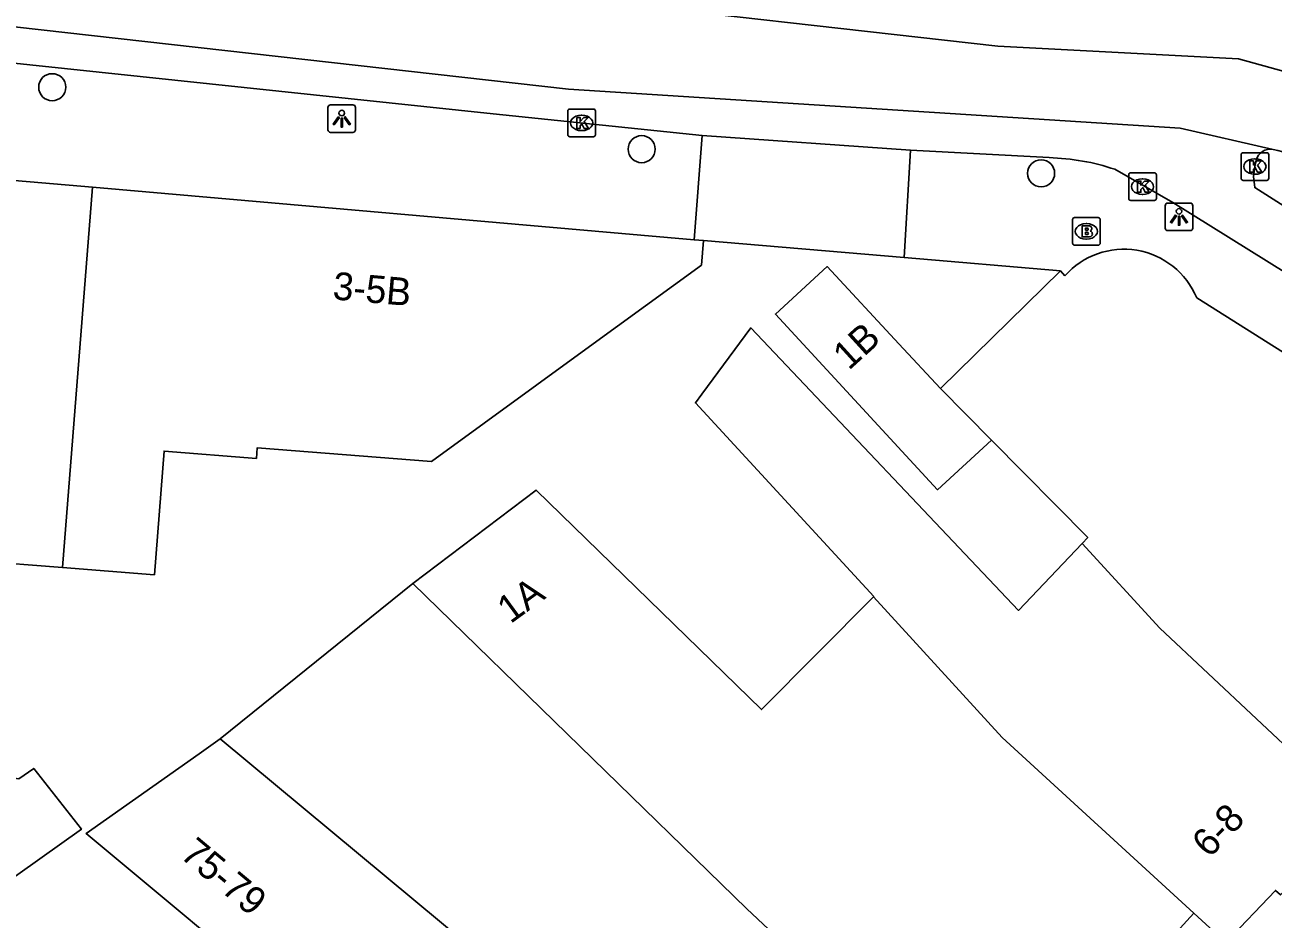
# Model space of a CAD drawing. Extents: x 160664 to 161506, y 382245 to 383288.
# Drawn here: x 160915.93 to 160961.04, y 382898.51 to 382930.82 of the extents above; entities that cross this region are included whole.
import ezdxf

# ---------------------------------------------------------------- set-up
doc = ezdxf.new("R2010")
doc.units = 0
for name, color, linetype in [('IMGEO_Boom', 7, 'Continuous'), ('IMGEO_Brandkraan', 7, 'Continuous'), ('IMGEO_Fietspad_gesloten', 7, 'Continuous'), ('IMGEO_Kolk', 7, 'Continuous'), ('IMGEO_Lichtpunt', 7, 'Continuous'), ('IMGEO_OVBaan_gesloten', 7, 'Continuous'), ('IMGEO_Pand', 7, 'Continuous'), ('IMGEO_Pand_nummerreeks', 7, 'Continuous'), ('IMGEO_Voetpad_open', 7, 'Continuous')]:
    doc.layers.add(name, color=color, linetype=linetype)

msp = doc.modelspace()

# ---------------------------------------------------------------- linework, layer by layer
at = {"layer": 'IMGEO_Boom'}
for centre in [(160916.911, 382928.573), (160938.215, 382926.333), (160952.653, 382925.461)]:
    msp.add_circle(centre, 0.489, dxfattribs=at)
at = {"layer": 'IMGEO_Brandkraan'}
for p, q in [((160953.787, 382922.935), (160953.787, 382923.787)), ((160953.862, 382923.861), (160954.714, 382923.861)), ((160954.275, 382923.641), (160954.3, 382923.641)), ((160954.788, 382923.787), (160954.788, 382922.935)), ((160954.714, 382922.861), (160953.862, 382922.861)), ((160954.298, 382923.081), (160954.273, 382923.081))]:
    msp.add_line(p, q, dxfattribs=at)
for points in [[(160953.787, 382922.935), (160953.787, 382923.787)], [(160953.862, 382923.861), (160954.714, 382923.861)], [(160954.788, 382923.787), (160954.788, 382922.935)], [(160954.135, 382923.561), (160954.135, 382923.161), (160954.348, 382923.161)], [(160954.366, 382923.561), (160954.135, 382923.561)], [(160954.314, 382923.48), (160954.26, 382923.48), (160954.26, 382923.404)], [(160954.26, 382923.404), (160954.313, 382923.404)], [(160954.322, 382923.328), (160954.26, 382923.328), (160954.26, 382923.247)], [(160954.26, 382923.247), (160954.322, 382923.247)], [(160954.714, 382922.861), (160953.862, 382922.861)]]:
    msp.add_lwpolyline(points, dxfattribs=at)
for centre, radius, start, end in [((160953.864, 382923.785), 0.0765, 91.552, 178.448), ((160953.864, 382923.785), 0.0765, 91.552, 178.448), ((160954.712, 382923.785), 0.0765, 1.552, 88.448), ((160954.712, 382923.785), 0.0765, 1.552, 88.448), ((160954.315, 382923.442), 0.0379, 267.8285, 90.9355), ((160954.323, 382923.287), 0.0404, 269.8759, 90.5077), ((160954.354, 382923.412), 0.251, 268.6676, 293.5347), ((160954.37, 382923.416), 0.145, 59.4692, 91.5367), ((160954.395, 382923.463), 0.0922, 285.5137, 58.1501), ((160954.4, 382923.271), 0.105, 301.3115, 78.989), ((160953.864, 382922.937), 0.0765, 181.552, 268.448), ((160953.864, 382922.937), 0.0765, 181.552, 268.448), ((160954.712, 382922.937), 0.0765, 271.552, 358.448), ((160954.712, 382922.937), 0.0765, 271.552, 358.448)]:
    msp.add_arc(centre, radius, start, end, dxfattribs=at)
for centre, major_axis, ratio, start_param, end_param in [((160954.274, 382923.361), (-0.387, 0.002), 0.722429, 4.712389, 7.853982), ((160954.299, 382923.361), (-0.39, 0.002), 0.717154, 1.570796, 4.712389)]:
    msp.add_ellipse(centre, major_axis=major_axis, ratio=ratio, start_param=start_param, end_param=end_param, dxfattribs=at)
at = {"layer": 'IMGEO_Fietspad_gesloten'}
for points in [[(160940.406, 382926.828), (160932.851, 382927.616), (160914.84, 382929.519), (160910.629, 382929.789), (160910.39, 382929.798)], [(160940.406, 382926.828), (160947.93, 382926.301)], [(160947.93, 382926.301), (160952.94, 382926.027)], [(160960.425, 382925.941), (160960.379, 382925.705), (160960.333, 382925.349), (160960.377, 382924.944), (160961.434, 382924.276)], [(160955.322, 382925.605), (160957.414, 382924.41), (160972.521, 382914.992), (160974.161, 382913.943)]]:
    msp.add_lwpolyline(points, dxfattribs=at)
for centre, radius, start, end in [((160952.712, 382917.807), 8.223, 71.4953, 88.4119), ((160960.928, 382925.812), 0.519, 78.1045, 165.6018)]:
    msp.add_arc(centre, radius, start, end, dxfattribs=at)
at = {"layer": 'IMGEO_Kolk'}
for p, q in [((160935.545, 382926.857), (160935.545, 382927.709)), ((160935.62, 382927.783), (160936.472, 382927.783)), ((160936.546, 382927.709), (160936.546, 382926.857)), ((160936.033, 382927.563), (160936.058, 382927.563)), ((160936.056, 382927.003), (160936.031, 382927.003)), ((160936.472, 382926.783), (160935.62, 382926.783)), ((160959.879, 382925.28), (160959.879, 382926.132)), ((160959.954, 382926.206), (160960.806, 382926.206)), ((160960.367, 382925.986), (160960.392, 382925.986)), ((160960.88, 382926.132), (160960.88, 382925.28)), ((160955.893, 382925.478), (160956.745, 382925.478)), ((160955.818, 382924.552), (160955.818, 382925.404)), ((160956.306, 382925.258), (160956.331, 382925.258)), ((160956.819, 382925.404), (160956.819, 382924.552)), ((160960.806, 382925.206), (160959.954, 382925.206)), ((160960.39, 382925.426), (160960.365, 382925.426)), ((160956.329, 382924.698), (160956.304, 382924.698)), ((160956.745, 382924.478), (160955.893, 382924.478))]:
    msp.add_line(p, q, dxfattribs=at)
for points in [[(160935.545, 382926.857), (160935.545, 382927.709)], [(160935.62, 382927.783), (160936.472, 382927.783)], [(160936.546, 382927.709), (160936.546, 382926.857)], [(160935.866, 382927.483), (160935.989, 382927.483), (160935.989, 382927.332), (160936.119, 382927.483), (160936.283, 382927.483), (160936.137, 382927.332), (160936.29, 382927.083), (160936.138, 382927.083), (160936.053, 382927.247), (160935.989, 382927.18), (160935.989, 382927.083), (160935.866, 382927.083), (160935.866, 382927.483)], [(160936.472, 382926.783), (160935.62, 382926.783)], [(160959.879, 382925.28), (160959.879, 382926.132)], [(160959.954, 382926.206), (160960.806, 382926.206)], [(160960.2, 382925.906), (160960.323, 382925.906), (160960.323, 382925.755), (160960.453, 382925.906), (160960.617, 382925.906), (160960.471, 382925.755), (160960.624, 382925.506), (160960.472, 382925.506), (160960.387, 382925.67), (160960.323, 382925.603), (160960.323, 382925.506), (160960.2, 382925.506), (160960.2, 382925.906)], [(160960.88, 382926.132), (160960.88, 382925.28)], [(160955.893, 382925.478), (160956.745, 382925.478)], [(160955.818, 382924.552), (160955.818, 382925.404)], [(160956.139, 382925.178), (160956.262, 382925.178), (160956.262, 382925.027), (160956.392, 382925.178), (160956.556, 382925.178), (160956.41, 382925.027), (160956.563, 382924.778), (160956.411, 382924.778), (160956.326, 382924.942), (160956.262, 382924.875), (160956.262, 382924.778), (160956.139, 382924.778), (160956.139, 382925.178)], [(160956.819, 382925.404), (160956.819, 382924.552)], [(160960.806, 382925.206), (160959.954, 382925.206)], [(160956.745, 382924.478), (160955.893, 382924.478)]]:
    msp.add_lwpolyline(points, dxfattribs=at)
for centre, start, end in [((160935.622, 382927.707), 91.552, 178.448), ((160935.622, 382927.707), 91.552, 178.448), ((160936.47, 382927.707), 1.552, 88.448), ((160936.47, 382927.707), 1.552, 88.448), ((160935.622, 382926.859), 181.552, 268.448), ((160935.622, 382926.859), 181.552, 268.448), ((160936.47, 382926.859), 271.552, 358.448), ((160936.47, 382926.859), 271.552, 358.448), ((160959.956, 382926.13), 91.552, 178.448), ((160959.956, 382926.13), 91.552, 178.448), ((160960.804, 382926.13), 1.552, 88.448), ((160960.804, 382926.13), 1.552, 88.448), ((160955.895, 382925.402), 91.552, 178.448), ((160955.895, 382925.402), 91.552, 178.448), ((160956.743, 382925.402), 1.552, 88.448), ((160956.743, 382925.402), 1.552, 88.448), ((160959.956, 382925.282), 181.552, 268.448), ((160959.956, 382925.282), 181.552, 268.448), ((160960.804, 382925.282), 271.552, 358.448), ((160960.804, 382925.282), 271.552, 358.448), ((160955.895, 382924.554), 181.552, 268.448), ((160955.895, 382924.554), 181.552, 268.448), ((160956.743, 382924.554), 271.552, 358.448), ((160956.743, 382924.554), 271.552, 358.448)]:
    msp.add_arc(centre, 0.0765, start, end, dxfattribs=at)
for centre, major_axis, ratio, start_param, end_param in [((160936.032, 382927.283), (-0.387, 0.002), 0.722429, 4.712389, 7.853982), ((160936.057, 382927.283), (-0.39, 0.002), 0.717154, 1.570796, 4.712389), ((160960.366, 382925.706), (-0.387, 0.002), 0.722429, 4.712389, 7.853982), ((160960.391, 382925.706), (-0.39, 0.002), 0.717154, 1.570796, 4.712389), ((160956.305, 382924.978), (-0.387, 0.002), 0.722429, 4.712389, 7.853982), ((160956.33, 382924.978), (-0.39, 0.002), 0.717154, 1.570796, 4.712389)]:
    msp.add_ellipse(centre, major_axis=major_axis, ratio=ratio, start_param=start_param, end_param=end_param, dxfattribs=at)
at = {"layer": 'IMGEO_Lichtpunt'}
for p, q in [((160926.876, 382927.84), (160926.876, 382927.033)), ((160926.876, 382927.84), (160926.876, 382927.033)), ((160927.778, 382927.935), (160926.97, 382927.935)), ((160927.778, 382927.935), (160926.97, 382927.935)), ((160927.872, 382927.033), (160927.872, 382927.84)), ((160927.872, 382927.033), (160927.872, 382927.84)), ((160926.97, 382926.939), (160927.778, 382926.939)), ((160926.97, 382926.939), (160927.778, 382926.939)), ((160957.138, 382924.29), (160957.138, 382923.483)), ((160957.138, 382924.29), (160957.138, 382923.483)), ((160958.04, 382924.385), (160957.232, 382924.385)), ((160958.04, 382924.385), (160957.232, 382924.385)), ((160958.134, 382923.483), (160958.134, 382924.29)), ((160958.134, 382923.483), (160958.134, 382924.29)), ((160957.232, 382923.389), (160958.04, 382923.389)), ((160957.232, 382923.389), (160958.04, 382923.389))]:
    msp.add_line(p, q, dxfattribs=at)
for points in [[(160927.25, 382927.504), (160927.289, 382927.476), (160927.101, 382927.214), (160927.063, 382927.241), (160927.25, 382927.504)], [(160927.352, 382927.456), (160927.399, 382927.456), (160927.399, 382927.134), (160927.352, 382927.134), (160927.352, 382927.456)], [(160927.462, 382927.476), (160927.5, 382927.503), (160927.687, 382927.241), (160927.648, 382927.213), (160927.462, 382927.476)], [(160957.512, 382923.954), (160957.551, 382923.926), (160957.363, 382923.664), (160957.325, 382923.691), (160957.512, 382923.954)], [(160957.614, 382923.906), (160957.661, 382923.906), (160957.661, 382923.584), (160957.614, 382923.584), (160957.614, 382923.906)], [(160957.724, 382923.926), (160957.762, 382923.953), (160957.949, 382923.691), (160957.91, 382923.663), (160957.724, 382923.926)]]:
    msp.add_lwpolyline(points, dxfattribs=at)
for centre in [(160927.375, 382927.638), (160957.637, 382924.088)]:
    msp.add_circle(centre, 0.0994, dxfattribs=at)
for centre, start, end in [((160926.97, 382927.84), 90, 180), ((160926.97, 382927.84), 90, 180), ((160927.778, 382927.84), 0, 90), ((160927.778, 382927.84), 0, 90), ((160926.97, 382927.033), 180, 270), ((160926.97, 382927.033), 180, 270), ((160927.778, 382927.033), 270, 0), ((160927.778, 382927.033), 270, 360), ((160957.232, 382924.29), 90, 180), ((160957.232, 382924.29), 90, 180), ((160958.04, 382924.29), 0, 90), ((160958.04, 382924.29), 0, 90), ((160957.232, 382923.483), 180, 270), ((160957.232, 382923.483), 180, 270), ((160958.04, 382923.483), 270, 0), ((160958.04, 382923.483), 270, 360)]:
    msp.add_arc(centre, 0.0946, start, end, dxfattribs=at)
at = {"layer": 'IMGEO_OVBaan_gesloten'}
for points in [[(160870.47, 382922.866), (160882.904, 382929.187), (160890.673, 382931.836), (160897.982, 382933.621), (160903.988, 382934.545), (160909.581, 382934.405), (160918.971, 382933.683), (160951.086, 382930.055), (160959.79, 382929.599), (160967.578, 382927.438), (160972.145, 382924.641), (160978.816, 382919.461), (160981.785, 382916.694)], [(160961.035, 382926.32), (160957.674, 382927.094), (160935.566, 382928.505), (160911.678, 382931.189), (160907.553, 382931.166), (160903.382, 382930.863), (160897.497, 382930.071), (160888.563, 382927.461), (160885.812, 382926.048)]]:
    msp.add_lwpolyline(points, dxfattribs=at)
msp.add_arc((160956.137, 382904.425), 22.436, 73.661, 77.391, dxfattribs=at)
at = {"layer": 'IMGEO_Pand'}
for points in [[(160918.365, 382924.954), (160912.298, 382925.482), (160912.132, 382925.497)], [(160917.281, 382911.212), (160918.365, 382924.954)], [(160918.365, 382924.954), (160940.114, 382923.06)], [(160940.445, 382923.031), (160940.375, 382922.144), (160936.334, 382919.201), (160930.624, 382915.042), (160924.32, 382915.538), (160924.29, 382915.158), (160920.955, 382915.421), (160920.602, 382910.95), (160917.281, 382911.212)], [(160940.445, 382923.031), (160940.114, 382923.06)], [(160950.858, 382915.82), (160948.904, 382914.021), (160943.051, 382920.375), (160944.914, 382922.091), (160947.512, 382919.302), (160949.015, 382917.688)], [(160949.015, 382917.688), (160953.353, 382921.931)], [(160953.512, 382921.758), (160953.353, 382921.931)], [(160969.406, 382913.715), (160969.504, 382913.879), (160958.277, 382920.962)], [(160946.591, 382910.148), (160946.603, 382910.159), (160940.155, 382917.163), (160940.39, 382917.481), (160942.156, 382919.874), (160951.834, 382909.663), (160954.133, 382912.08)], [(160950.858, 382915.82), (160949.015, 382917.688)], [(160911.41, 382916.36), (160911.398, 382916.231), (160914.522, 382915.935), (160914.169, 382911.457), (160917.281, 382911.212)], [(160954.133, 382912.08), (160954.337, 382912.294), (160950.858, 382915.82)], [(160929.946, 382910.637), (160934.398, 382914.01), (160942.541, 382906.075), (160946.591, 382910.148)], [(160963.933, 382902.47), (160956.94, 382909.02), (160954.133, 382912.08)], [(160922.98, 382905.016), (160929.946, 382910.637)], [(160951.057, 382890.389), (160942.018, 382898.873), (160929.946, 382910.637)], [(160958.177, 382898.714), (160951.249, 382905.071), (160946.591, 382910.148)], [(160900.762, 382902.712), (160905.255, 382904.907), (160908.804, 382906.641), (160909.267, 382904.892), (160910.326, 382904.753), (160910.366, 382904.283), (160915.705, 382903.57), (160916.245, 382903.951), (160917.966, 382901.753), (160913.445, 382898.535), (160913.261, 382898.405), (160909.045, 382895.403)], [(160931.944, 382889.847), (160932.062, 382889.988), (160925.745, 382895.256), (160918.136, 382901.602), (160922.223, 382904.483), (160922.98, 382905.016)], [(160946.792, 382885.259), (160936.856, 382893.234), (160936.985, 382893.375), (160922.98, 382905.016)], [(160958.177, 382898.714), (160959.329, 382897.657), (160961.123, 382899.543), (160961.3, 382899.375), (160962.405, 382900.537), (160962.242, 382900.693), (160963.933, 382902.47)], [(160951.057, 382890.389), (160956.948, 382896.81), (160956.667, 382897.068), (160958.177, 382898.714)]]:
    msp.add_lwpolyline(points, dxfattribs=at)
msp.add_arc((160955.645, 382919.864), 2.852, 22.6473, 138.3851, dxfattribs=at)
at = {"layer": 'IMGEO_Voetpad_open'}
for points in [[(160940.114, 382923.06), (160940.406, 382926.828)], [(160947.698, 382922.415), (160947.93, 382926.301)], [(160947.698, 382922.415), (160940.445, 382923.031)], [(160953.353, 382921.931), (160947.698, 382922.415)]]:
    msp.add_lwpolyline(points, dxfattribs=at)

# ---------------------------------------------------------------- texts
at = {"layer": 'IMGEO_Pand_nummerreeks'}
for s, rotation, p in [('3-5B', 355.0225, (160927.024, 382920.907)), ('1B', 42.2148, (160945.699, 382918.314)), ('1A', 36.1896, (160933.472, 382909.158)), ('6-8', 46.2627, (160958.735, 382900.681)), ('75-79', 320.1737, (160921.488, 382900.759))]:
    msp.add_text(s, height=1, rotation=rotation, dxfattribs=at).set_placement(p)

doc.saveas('drawing.dxf')
